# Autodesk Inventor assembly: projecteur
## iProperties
Created: 2011-01
Part Number: projecteur
Document SubType Name: Assembly
Designer: eric
Norme de conversion: IGES 5.3
Nom du fichier: No Iges File Name specified
Préprocesseur: Autodesk Inventor 2011
Postprocesseur: Build: 342, Release: 2008 SP3 - Date: Tue 05/27/2008
Unités envoyées: MM
Incertitude: 0.01
Author: eric
